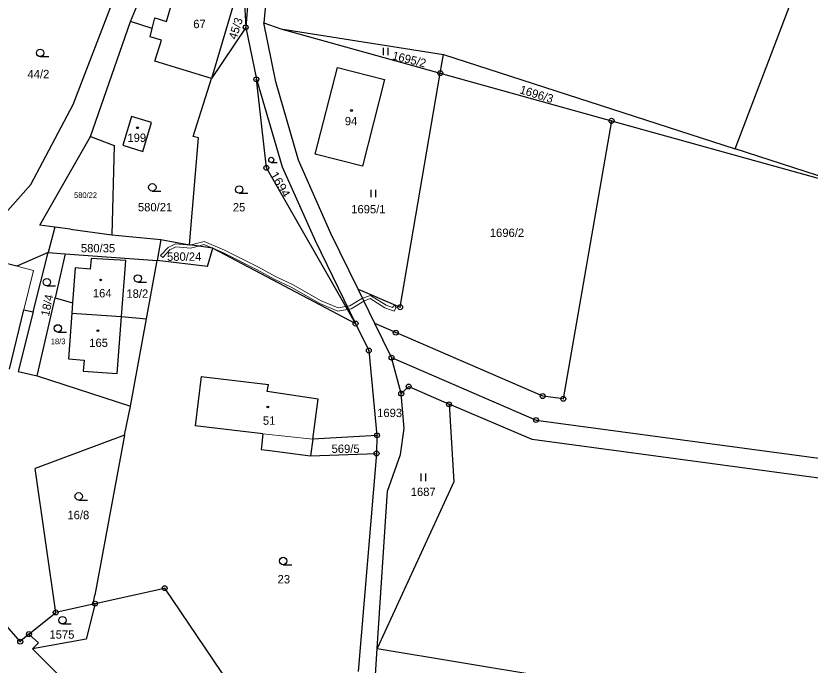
# Model space of a CAD drawing. Extents: x -601131 to -597152, y -1058536 to -1055911.
# Drawn here: x -599420.5 to -599259.4, y -1057555.3 to -1057423.7 of the extents above; entities that cross this region are included whole.
import ezdxf
from ezdxf.enums import TextEntityAlignment as Align

# ---------------------------------------------------------------- set-up
doc = ezdxf.new("R2010")
doc.units = 0
doc.header["$LTSCALE"] = 0.68
for name, color, linetype, lineweight in [('1', 7, 'Continuous', 25), ('13', 7, 'Continuous', 13), ('3', 7, 'Continuous', 25), ('4', 7, 'Continuous', 13), ('5', 7, 'Continuous', 25), ('8', 7, 'Continuous', 25)]:
    doc.layers.add(name, color=color, linetype=linetype, lineweight=lineweight)
doc.layers.add('2', color=7, linetype='Continuous')

msp = doc.modelspace()

# ---------------------------------------------------------------- linework, layer by layer
at = {"layer": '1'}
for p, q in [((-599397.22, -1057424.81), (-599389.32, -1057405.57)), ((-599389.98, -1057424.78), (-599386.04, -1057411.48)), ((-599374.47, -1057414.85), (-599380.85, -1057436.39)), ((-599374.41, -1057414.64), (-599373.88, -1057426.01)), ((-599373, -1057414.71), (-599373.88, -1057426.01)), ((-599369.37, -1057415.48), (-599370.18, -1057425.11)), ((-599274.58, -1057450.67), (-599261.4, -1057415.87)), ((-599408.91, -1057441.67), (-599400.99, -1057421.07)), ((-599392.84, -1057426.25), (-599392.3, -1057424.09)), ((-599392.3, -1057424.09), (-599389.98, -1057424.78)), ((-599405.38, -1057448.15), (-599397.22, -1057424.81)), ((-599392.84, -1057426.25), (-599397.22, -1057424.81)), ((-599370.18, -1057425.11), (-599366.77, -1057426.3)), ((-599367.79, -1057437.07), (-599370.18, -1057425.11)), ((-599393.25, -1057427.9), (-599392.84, -1057426.25)), ((-599373.88, -1057426.01), (-599380.85, -1057436.39)), ((-599373.88, -1057426.01), (-599371.72, -1057436.53)), ((-599366.77, -1057426.3), (-599333.75, -1057431.48)), ((-599366.77, -1057426.3), (-599334.41, -1057435.3)), ((-599390.98, -1057428.6), (-599393.25, -1057427.9)), ((-599392.3, -1057432.88), (-599390.98, -1057428.6)), ((-599334.41, -1057435.3), (-599333.75, -1057431.48)), ((-599333.75, -1057431.48), (-599274.58, -1057450.67)), ((-599380.85, -1057436.39), (-599392.3, -1057432.88)), ((-599359.78, -1057451.69), (-599355.29, -1057434.16)), ((-599355.29, -1057434.16), (-599345.76, -1057436.59)), ((-599342.56, -1057482.76), (-599334.41, -1057435.3)), ((-599334.41, -1057435.3), (-599299.66, -1057444.95)), ((-599384.55, -1057448.11), (-599380.85, -1057436.39)), ((-599369.69, -1057454.48), (-599371.72, -1057436.53)), ((-599371.72, -1057436.53), (-599366.5, -1057454.29)), ((-599363.19, -1057452.94), (-599367.79, -1057437.07)), ((-599345.76, -1057436.59), (-599350.21, -1057454.18)), ((-599417.49, -1057457.87), (-599408.91, -1057441.67)), ((-599299.66, -1057444.95), (-599309.46, -1057501.34)), ((-599299.66, -1057444.95), (-599247.53, -1057459.44)), ((-599415.66, -1057466.11), (-599405.38, -1057448.15)), ((-599405.38, -1057448.15), (-599400.53, -1057449.94)), ((-599383.48, -1057448.43), (-599384.55, -1057448.11)), ((-599400.53, -1057449.94), (-599401.06, -1057468.07)), ((-599385.26, -1057470.08), (-599383.48, -1057448.43)), ((-599247.53, -1057459.44), (-599274.58, -1057450.67)), ((-599356.59, -1057467.78), (-599363.19, -1057452.94)), ((-599350.21, -1057454.18), (-599359.78, -1057451.69)), ((-599351.6, -1057486.08), (-599369.69, -1057454.48)), ((-599366.5, -1057454.29), (-599359.77, -1057469.25)), ((-599430.01, -1057472.01), (-599417.49, -1057457.87)), ((-599412.59, -1057466.52), (-599415.66, -1057466.11)), ((-599412.59, -1057466.52), (-599413.95, -1057471.67)), ((-599409.45, -1057466.94), (-599412.59, -1057466.52)), ((-599409.45, -1057466.94), (-599401.06, -1057468.07)), ((-599401.06, -1057468.07), (-599391.07, -1057469.03)), ((-599391.07, -1057469.03), (-599391.85, -1057473.27)), ((-599391.07, -1057469.03), (-599385.26, -1057470.08)), ((-599359.77, -1057469.25), (-599351.6, -1057486.08)), ((-599351.09, -1057479.07), (-599356.59, -1057467.78)), ((-599380.53, -1057470.79), (-599385.26, -1057470.08)), ((-599381.63, -1057474.48), (-599380.53, -1057470.79)), ((-599380.53, -1057470.79), (-599351.6, -1057486.08)), ((-599413.95, -1057471.67), (-599420.32, -1057474.45)), ((-599416.99, -1057483.72), (-599413.95, -1057471.67)), ((-599413.95, -1057471.67), (-599410.52, -1057471.94)), ((-599410.52, -1057471.94), (-599412.56, -1057480.84)), ((-599410.52, -1057471.94), (-599391.85, -1057473.27)), ((-599420.32, -1057474.45), (-599423.48, -1057473.61)), ((-599405.24, -1057472.85), (-599405.46, -1057475.05)), ((-599398.2, -1057473.31), (-599405.24, -1057472.85)), ((-599399.06, -1057484.67), (-599398.2, -1057473.31)), ((-599394.02, -1057485.14), (-599391.85, -1057473.27)), ((-599381.63, -1057474.48), (-599391.85, -1057473.27)), ((-599408.47, -1057474.75), (-599409, -1057481.85)), ((-599405.46, -1057475.05), (-599408.47, -1057474.75)), ((-599347.67, -1057486.08), (-599351.09, -1057479.07)), ((-599351.09, -1057479.07), (-599342.56, -1057482.76)), ((-599416.17, -1057496.65), (-599412.56, -1057480.84)), ((-599412.56, -1057480.84), (-599409, -1057481.85)), ((-599409, -1057481.85), (-599409.16, -1057484)), ((-599421.79, -1057495.35), (-599418.87, -1057483.31)), ((-599416.99, -1057483.72), (-599420.03, -1057495.78)), ((-599418.87, -1057483.31), (-599416.99, -1057483.72)), ((-599409.16, -1057484), (-599409.85, -1057493.25)), ((-599409.16, -1057484), (-599399.06, -1057484.67)), ((-599399.94, -1057496.2), (-599399.06, -1057484.67)), ((-599399.06, -1057484.67), (-599394.02, -1057485.14)), ((-599397.27, -1057502.85), (-599394.02, -1057485.14)), ((-599351.6, -1057486.08), (-599348.91, -1057491.55)), ((-599343.44, -1057487.91), (-599347.67, -1057486.08)), ((-599344.31, -1057492.98), (-599347.67, -1057486.08)), ((-599313.64, -1057500.78), (-599343.44, -1057487.91)), ((-599348.91, -1057491.55), (-599347.25, -1057508.75)), ((-599409.85, -1057493.25), (-599406.67, -1057493.49)), ((-599342.33, -1057500.28), (-599344.31, -1057492.98)), ((-599344.31, -1057492.98), (-599314.99, -1057505.64)), ((-599406.67, -1057493.49), (-599406.84, -1057495.73)), ((-599420.03, -1057495.78), (-599416.17, -1057496.65)), ((-599416.17, -1057496.65), (-599397.27, -1057502.85)), ((-599406.84, -1057495.73), (-599399.94, -1057496.2)), ((-599382.94, -1057496.84), (-599384.12, -1057506.83)), ((-599382.94, -1057496.84), (-599369.29, -1057498.45)), ((-599369.5, -1057499.88), (-599369.29, -1057498.45)), ((-599359.16, -1057501.39), (-599369.5, -1057499.88)), ((-599342.33, -1057500.28), (-599340.82, -1057498.85)), ((-599340.82, -1057498.85), (-599332.64, -1057502.45)), ((-599360.26, -1057509.55), (-599359.16, -1057501.39)), ((-599341.71, -1057507.38), (-599342.33, -1057500.28)), ((-599309.46, -1057501.34), (-599313.64, -1057500.78)), ((-599398.45, -1057508.73), (-599397.27, -1057502.85)), ((-599315.77, -1057509.56), (-599332.64, -1057502.45)), ((-599332.64, -1057502.45), (-599331.64, -1057518.18)), ((-599314.99, -1057505.64), (-599237.96, -1057516.04)), ((-599370.38, -1057508.44), (-599384.12, -1057506.83)), ((-599342.45, -1057512.6), (-599341.71, -1057507.38)), ((-599398.45, -1057508.73), (-599416.62, -1057515.48)), ((-599398.45, -1057508.73), (-599404.51, -1057541.18)), ((-599370.38, -1057508.44), (-599370.66, -1057511.06)), ((-599360.26, -1057509.55), (-599360.71, -1057512.9)), ((-599347.25, -1057508.75), (-599360.26, -1057509.55)), ((-599347.25, -1057508.75), (-599347.34, -1057512.42)), ((-599238.7, -1057519.97), (-599315.77, -1057509.56)), ((-599370.66, -1057511.06), (-599370.72, -1057511.62)), ((-599370.72, -1057511.62), (-599369.56, -1057511.77)), ((-599369.56, -1057511.77), (-599361.28, -1057512.83)), ((-599360.71, -1057512.9), (-599347.34, -1057512.42)), ((-599347.34, -1057512.42), (-599351.06, -1057556.67)), ((-599345.14, -1057520.1), (-599342.45, -1057512.6)), ((-599361.28, -1057512.83), (-599360.71, -1057512.9)), ((-599412.42, -1057544.66), (-599416.62, -1057515.48)), ((-599331.64, -1057518.18), (-599347.19, -1057551.97)), ((-599347.19, -1057551.97), (-599345.14, -1057520.1)), ((-599404.44, -1057542.88), (-599390.32, -1057539.74)), ((-599390.32, -1057539.74), (-599371.44, -1057567.75)), ((-599404.84, -1057542.97), (-599404.51, -1057541.18)), ((-599404.84, -1057542.97), (-599412.42, -1057544.66)), ((-599404.44, -1057542.88), (-599406.22, -1057550.11)), ((-599404.44, -1057542.88), (-599404.84, -1057542.97)), ((-599417.85, -1057549.05), (-599412.42, -1057544.66)), ((-599419.62, -1057550.58), (-599422.72, -1057547)), ((-599417.85, -1057549.05), (-599419.62, -1057550.58)), ((-599415.93, -1057550.81), (-599417.85, -1057549.05)), ((-599406.22, -1057550.11), (-599417.11, -1057552.04)), ((-599417.11, -1057552.04), (-599415.93, -1057550.81)), ((-599403.43, -1057565.64), (-599417.11, -1057552.04)), ((-599347.53, -1057557.31), (-599347.19, -1057551.97)), ((-599347.19, -1057551.97), (-599313.01, -1057557.68))]:
    msp.add_line(p, q, dxfattribs=at)
msp.add_lwpolyline([(-599398.78, -1057449.9), (-599394.76, -1057451.19), (-599392.99, -1057445.3), (-599397.03, -1057444.09)], close=True, dxfattribs=at)
at = {"layer": '13'}
for points in [[(-599385.08, -1057470.79), (-599383.45, -1057470.35), (-599384.92, -1057470.13), (-599385.12, -1057470.19), (-599388.14, -1057469.88), (-599389.6, -1057470.65), (-599391.13, -1057472.28), (-599390.7, -1057472.69), (-599389.24, -1057471.13), (-599388.02, -1057470.5)], [(-599371.29, -1057474.63), (-599378.15, -1057471.16), (-599382.3, -1057469.42), (-599384.92, -1057470.13), (-599383.45, -1057470.35), (-599382.34, -1057470.06), (-599380.53, -1057470.79), (-599378.41, -1057471.7), (-599371.57, -1057475.15), (-599368.1, -1057477.1), (-599364.69, -1057478.72), (-599358.86, -1057482.02), (-599355.2, -1057483.53), (-599353.25, -1057483.19), (-599353.03, -1057483.14), (-599353.3, -1057482.58), (-599353.57, -1057482.63), (-599355.14, -1057482.91), (-599358.6, -1057481.48), (-599364.41, -1057478.18), (-599367.82, -1057476.56)], [(-599343.78, -1057483.56), (-599343.39, -1057482.79), (-599343.51, -1057482.73), (-599343.41, -1057482.53), (-599343.71, -1057482.38), (-599343.81, -1057482.58), (-599343.92, -1057482.52), (-599344.08, -1057482.82), (-599345.37, -1057482.35), (-599348.55, -1057480.35), (-599350.17, -1057480.95), (-599349.91, -1057481.5), (-599348.61, -1057481.01), (-599345.63, -1057482.89)], [(-599352.52, -1057483.06), (-599349.91, -1057481.5), (-599350.17, -1057480.95), (-599352.74, -1057482.48), (-599353.3, -1057482.58), (-599353.03, -1057483.14)]]:
    msp.add_lwpolyline(points, close=True, dxfattribs=at)
at = {"layer": '3'}
for p, q in [((-599345.951, -1057431.64), (-599345.951, -1057430.14)), ((-599344.95, -1057431.64), (-599344.95, -1057430.14)), ((-599415.573, -1057431.94), (-599413.823, -1057431.94)), ((-599368.695, -1057453.4), (-599367.47, -1057453.4)), ((-599392.823, -1057459.2), (-599391.073, -1057459.2)), ((-599348.461, -1057460.44), (-599348.461, -1057458.94)), ((-599347.46, -1057460.44), (-599347.46, -1057458.94)), ((-599375.213, -1057459.65), (-599373.463, -1057459.65)), ((-599414.203, -1057478.43), (-599412.453, -1057478.43)), ((-599395.773, -1057477.67), (-599394.023, -1057477.67)), ((-599411.983, -1057487.8), (-599410.233, -1057487.8)), ((-599338.321, -1057518.01), (-599338.321, -1057516.51)), ((-599337.32, -1057518.01), (-599337.32, -1057516.51)), ((-599407.753, -1057521.87), (-599406.003, -1057521.87)), ((-599366.283, -1057534.98), (-599364.533, -1057534.98)), ((-599411.043, -1057547), (-599409.293, -1057547))]:
    msp.add_line(p, q, dxfattribs=at)
for centre, radius in [((-599415.5729, -1057431.1898), 0.75), ((-599368.695, -1057452.8749), 0.525), ((-599392.8229, -1057458.4498), 0.75), ((-599375.2129, -1057458.8998), 0.75), ((-599414.2029, -1057477.6798), 0.75), ((-599395.7729, -1057476.9198), 0.75), ((-599411.9829, -1057487.0498), 0.75), ((-599407.7529, -1057521.1198), 0.75), ((-599366.2829, -1057534.2298), 0.75), ((-599411.0429, -1057546.2498), 0.75)]:
    msp.add_circle(centre, radius, dxfattribs=at)
at = {"layer": '4'}
for p, q in [((-599420.32, -1057474.45), (-599416.94, -1057475.34)), ((-599416.94, -1057475.34), (-599418.87, -1057483.31)), ((-599360.26, -1057509.55), (-599370.38, -1057508.44))]:
    msp.add_line(p, q, dxfattribs=at)
at = {"layer": '5'}
for centre in [(-599352.4168, -1057442.8592), (-599395.8268, -1057446.3692), (-599403.3068, -1057477.2292), (-599403.8668, -1057487.5192), (-599369.4068, -1057502.9892)]:
    msp.add_circle(centre, 0.175, dxfattribs=at)
at = {"layer": '8'}
for centre, radius in [((-599373.88, -1057426.0099), 0.5), ((-599373.88, -1057426.0099), 0.0303), ((-599334.41, -1057435.2999), 0.5), ((-599334.41, -1057435.2999), 0.0303), ((-599371.72, -1057436.5299), 0.5), ((-599371.72, -1057436.5299), 0.0303), ((-599299.66, -1057444.9499), 0.5), ((-599299.66, -1057444.9499), 0.0303), ((-599369.69, -1057454.4799), 0.5), ((-599369.69, -1057454.4799), 0.0303), ((-599342.56, -1057482.7599), 0.5), ((-599342.56, -1057482.7599), 0.0303), ((-599351.6, -1057486.0799), 0.5), ((-599351.6, -1057486.0799), 0.0303), ((-599343.44, -1057487.9099), 0.5), ((-599343.44, -1057487.9099), 0.0303), ((-599348.91, -1057491.5499), 0.5), ((-599348.91, -1057491.5499), 0.0303), ((-599344.31, -1057492.9799), 0.5), ((-599344.31, -1057492.9799), 0.0303), ((-599342.33, -1057500.2799), 0.5), ((-599340.82, -1057498.8499), 0.5), ((-599340.82, -1057498.8499), 0.0303), ((-599342.33, -1057500.2799), 0.0303), ((-599313.64, -1057500.7799), 0.5), ((-599313.64, -1057500.7799), 0.0303), ((-599309.46, -1057501.3399), 0.5), ((-599309.46, -1057501.3399), 0.0303), ((-599332.64, -1057502.4499), 0.5), ((-599332.64, -1057502.4499), 0.0303), ((-599314.99, -1057505.6399), 0.5), ((-599314.99, -1057505.6399), 0.0303), ((-599347.25, -1057508.7499), 0.5), ((-599347.25, -1057508.7499), 0.0303), ((-599347.34, -1057512.4199), 0.5), ((-599347.34, -1057512.4199), 0.0303), ((-599390.32, -1057539.7399), 0.5), ((-599390.32, -1057539.7399), 0.0303), ((-599404.44, -1057542.8799), 0.5), ((-599404.44, -1057542.8799), 0.0303), ((-599412.42, -1057544.6599), 0.5), ((-599412.42, -1057544.6599), 0.0303), ((-599417.85, -1057549.0499), 0.5), ((-599417.85, -1057549.0499), 0.0303), ((-599419.62, -1057550.5799), 0.5), ((-599419.62, -1057550.5799), 0.0303)]:
    msp.add_circle(centre, radius, dxfattribs=at)

# ---------------------------------------------------------------- texts
at = {"layer": '2'}
for s, rotation, p in [('45/3', 72, (-599375.785, -1057428.591)), ('1695/2', 346, (-599344.282, -1057432.472)), ('1696/3', 343, (-599318.444, -1057439.346)), ('18/4', 78, (-599413.794, -1057484.708))]:
    msp.add_text(s, height=1.7, rotation=rotation, dxfattribs=at).set_placement(p)
for s, height, p in [('67', 1.7, (-599384.52, -1057426.165)), ('44/2', 1.7, (-599418.14, -1057436.324)), ('580/22', 1.14, (-599408.71, -1057460.605)), ('580/21', 1.7, (-599395.74, -1057463.314)), ('25', 1.7, (-599376.49, -1057463.334)), ('1695/1', 1.7, (-599352.47, -1057463.725)), ('1696/2', 1.7, (-599324.36, -1057468.515)), ('580/35', 1.7, (-599407.31, -1057471.635)), ('580/24', 1.7, (-599389.84, -1057473.344)), ('164', 1.7, (-599404.88, -1057480.765)), ('18/2', 1.7, (-599398.08, -1057480.854)), ('18/3', 1.14, (-599413.41, -1057490.255)), ('165', 1.7, (-599405.61, -1057490.824)), ('51', 1.7, (-599370.4, -1057506.604)), ('569/5', 1.7, (-599356.46, -1057512.314)), ('16/8', 1.7, (-599410.04, -1057525.755)), ('23', 1.7, (-599367.41, -1057538.775))]:
    msp.add_text(s, height=height, dxfattribs=at).set_placement(p)
for s, p in [('94', (-599352.509, -1057445.862)), ('199', (-599395.979, -1057449.235)), ('1693', (-599344.69, -1057505.042)), ('1687', (-599337.88, -1057521.052)), ('1575', (-599411.16, -1057549.992))]:
    msp.add_text(s, height=1.7, dxfattribs=at).set_placement(p, align=Align.CENTER)
at = {"layer": '2', "width": 1.1}
msp.add_text('1694', height=1.7, rotation=300, dxfattribs=at).set_placement((-599367.5954, -1057458.277), align=Align.CENTER)

doc.saveas('drawing.dxf')
